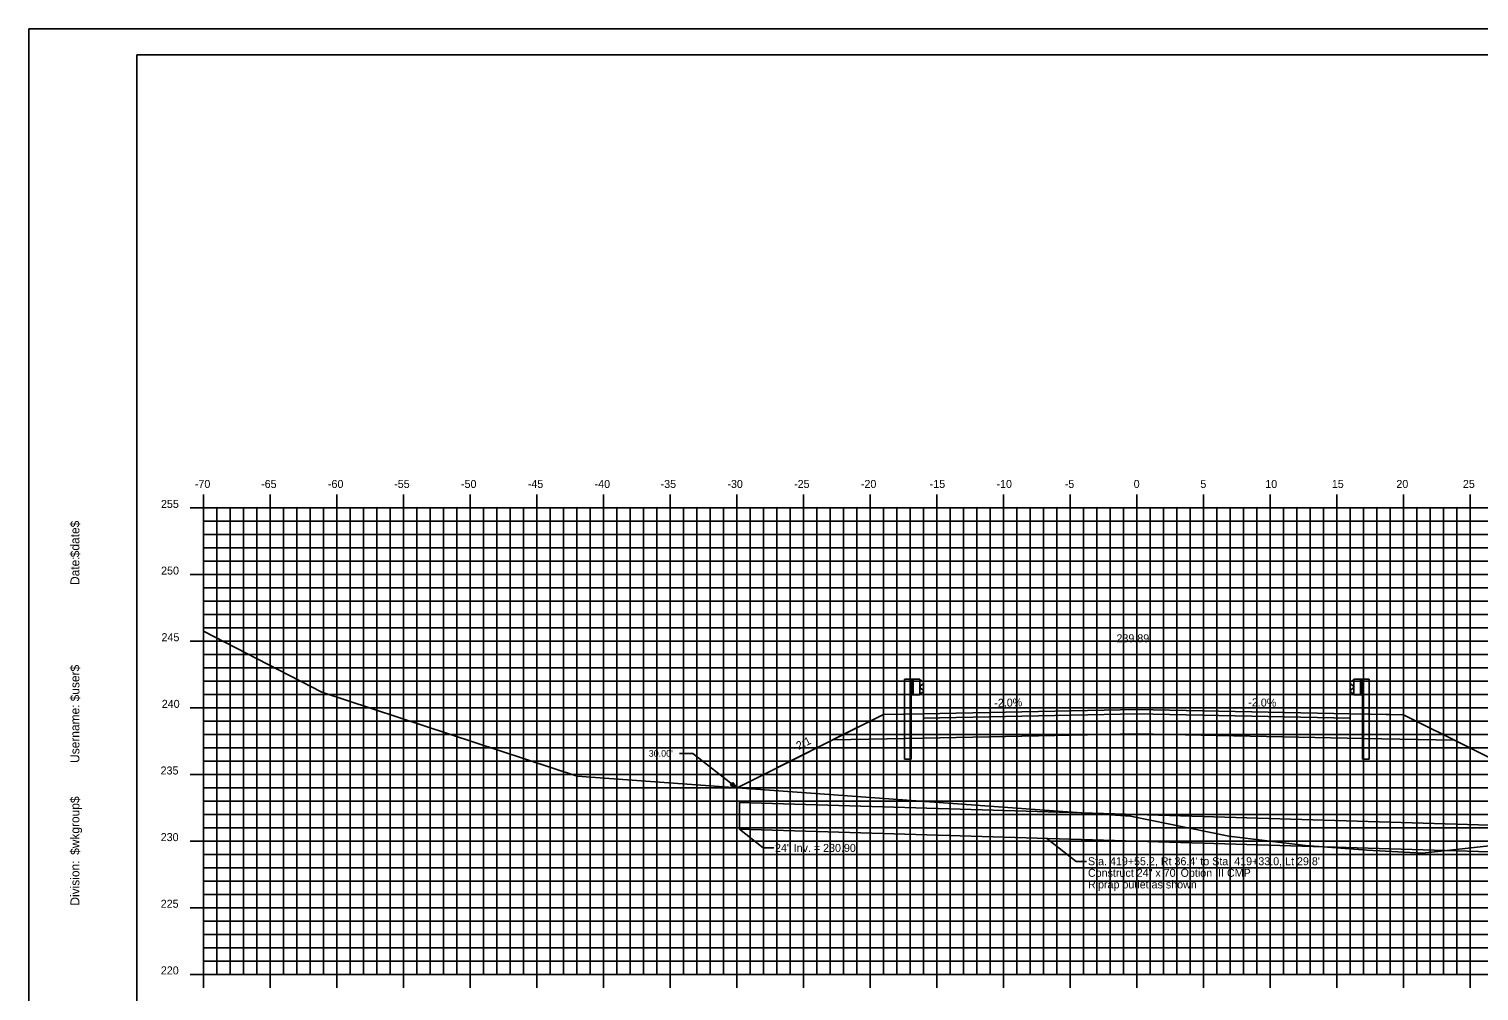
# Model space of a CAD drawing. Extents: x 1160718 to 1173142, y 616002 to 617630.
# Drawn here: x 1169214 to 1169322.8, y 616651.7 to 616723.9 of the extents above; entities that cross this region are included whole.
import ezdxf

# ---------------------------------------------------------------- set-up
doc = ezdxf.new("R2010")
doc.units = 0
for name, color, linetype in [('ANNOTATION', 7, 'Continuous'), ('BORDER', 7, 'Continuous'), ('D_Drainage_Culvert', 7, 'Continuous'), ('D_Guardrail_Beam_Lt', 7, 'Continuous'), ('D_Guardrail_Beam_Rt', 7, 'Continuous'), ('D_Roadway_Centerline', 7, 'Continuous'), ('D_Roadway_Centerline_Text', 7, 'Continuous'), ('D_Roadway_Edge_Shoulder', 7, 'Continuous'), ('D_Roadway_Edge_TW', 7, 'Continuous'), ('D_Roadway_Pavement', 7, 'Continuous'), ('D_Roadway_SlopeLines', 7, 'Continuous'), ('D_Roadway_SubGrade', 7, 'Continuous'), ('H_V ANNOTATION', 7, 'Continuous'), ('MAJOR', 7, 'Continuous'), ('MINOR', 7, 'Continuous'), ('PLOT BOUNDARY', 7, 'Continuous'), ('S_Roadway_Centerline', 7, 'Continuous')]:
    doc.layers.add(name, color=color, linetype=linetype)

msp = doc.modelspace()

# ---------------------------------------------------------------- linework, layer by layer
at = {"layer": 'ANNOTATION'}
for p in [(1169262.82, 616669.51), (1169267.12, 616666.93)]:
    msp.add_line(p, (1169263.82, 616669.51), dxfattribs=at)
msp.add_lwpolyline([(1169274.3, 616670.53), (1169281.12, 616670.66), (1169297.12, 616670.98), (1169314.12, 616670.64), (1169320.94, 616670.51)], dxfattribs=at)
msp.add_lwpolyline([(1169266.81, 616667.34), (1169267.12, 616666.93), (1169266.65, 616667.14)], close=True, dxfattribs=at)
at = {"layer": 'BORDER'}
for p, q in [((1169382.12, 616721.93), (1169222.12, 616721.93)), ((1169222.12, 616721.93), (1169222.12, 616616.93))]:
    msp.add_line(p, q, dxfattribs=at)
at = {"layer": 'D_Drainage_Culvert'}
for p, q in [((1169267.32, 616663.83), (1169267.32, 616665.83)), ((1169333.52, 616663.83), (1169267.32, 616665.83)), ((1169333.52, 616661.83), (1169267.32, 616663.83))]:
    msp.add_line(p, q, dxfattribs=at)
at = {"layer": 'D_Guardrail_Beam_Lt'}
for p, q in [((1169279.7, 616675.08), (1169279.7, 616669.08)), ((1169280.17, 616675.08), (1169279.7, 616675.08)), ((1169280.85, 616675.08), (1169280.17, 616675.08)), ((1169280.17, 616675.08), (1169280.17, 616673.91)), ((1169280.23, 616675.08), (1169280.23, 616673.91)), ((1169280.33, 616675.08), (1169280.33, 616673.91)), ((1169280.85, 616673.91), (1169280.85, 616675.08)), ((1169280.85, 616674.99), (1169280.93, 616674.98)), ((1169280.86, 616674.53), (1169280.86, 616674.46)), ((1169281.09, 616674.73), (1169280.89, 616674.59)), ((1169280.89, 616674.4), (1169281.09, 616674.26)), ((1169280.94, 616674.97), (1169281.09, 616674.87)), ((1169281.09, 616674.12), (1169280.94, 616674.02)), ((1169280.17, 616673.91), (1169280.85, 616673.91)), ((1169280.19, 616669.08), (1169280.19, 616673.91)), ((1169280.93, 616674.01), (1169280.85, 616673.99)), ((1169280.19, 616669.08), (1169279.7, 616669.08))]:
    msp.add_line(p, q, dxfattribs=at)
for centre, major_axis, start_param, end_param in [((1169280.94, 616674.53), (-0.0789, 0), 5.323254, 6.283185), ((1169280.94, 616674.46), (-0.0789, 0), 6.283185, 7.243116), ((1169280.92, 616674.94), (0.0417, 0), 0.959931, 1.376053), ((1169281.04, 616674.8), (0.0877, 0), 5.323254, 7.243116), ((1169281.04, 616674.19), (0.0877, 0), 5.323254, 7.243116), ((1169280.92, 616674.05), (0.0417, 0), 4.907132, 5.323254)]:
    msp.add_ellipse(centre, major_axis=major_axis, ratio=0.995501, start_param=start_param, end_param=end_param, dxfattribs=at)
at = {"layer": 'D_Guardrail_Beam_Rt'}
for p, q in [((1169313.29, 616674.97), (1169313.14, 616674.87)), ((1169313.14, 616674.73), (1169313.34, 616674.59)), ((1169313.34, 616674.4), (1169313.14, 616674.26)), ((1169313.14, 616674.12), (1169313.29, 616674.02)), ((1169313.38, 616675), (1169313.3, 616674.98)), ((1169313.37, 616674.53), (1169313.37, 616674.46)), ((1169313.38, 616675.08), (1169314.06, 616675.08)), ((1169313.38, 616673.91), (1169313.38, 616675.08)), ((1169313.9, 616675.08), (1169313.9, 616673.91)), ((1169314, 616675.08), (1169314, 616673.91)), ((1169314.06, 616675.08), (1169314.53, 616675.08)), ((1169314.06, 616675.08), (1169314.06, 616673.91)), ((1169314.53, 616675.08), (1169314.53, 616669.08)), ((1169313.3, 616674.01), (1169313.38, 616674)), ((1169314.06, 616673.91), (1169313.38, 616673.91)), ((1169314.04, 616669.08), (1169314.04, 616673.91)), ((1169314.04, 616669.08), (1169314.53, 616669.08))]:
    msp.add_line(p, q, dxfattribs=at)
for centre, major_axis, start_param, end_param in [((1169313.19, 616674.8), (-0.0877, 0), 5.323254, 7.243116), ((1169313.19, 616674.19), (-0.0877, 0), 5.323254, 7.243116), ((1169313.31, 616674.94), (-0.0417, 0), 4.907132, 5.323254), ((1169313.29, 616674.53), (0.0789, 0), 0, 0.959931), ((1169313.29, 616674.46), (0.0789, 0), 5.323254, 6.283185), ((1169313.31, 616674.05), (-0.0417, 0), 0.959931, 1.376053)]:
    msp.add_ellipse(centre, major_axis=major_axis, ratio=0.995501, start_param=start_param, end_param=end_param, dxfattribs=at)
at = {"layer": 'D_Roadway_Centerline'}
for p, q in [((1169273.26, 616670), (1169278.12, 616672.43)), ((1169278.12, 616672.43), (1169281.12, 616672.49)), ((1169281.12, 616672.49), (1169297.12, 616672.81)), ((1169297.12, 616672.81), (1169313.12, 616672.49)), ((1169313.12, 616672.49), (1169316.12, 616672.43)), ((1169267.13, 616666.94), (1169273.26, 616670)), ((1169321.99, 616669.98), (1169329.7, 616666.13))]:
    msp.add_line(p, q, dxfattribs=at)
at = {"layer": 'D_Roadway_Centerline_Text'}
for p, q in [((1169269.09, 616662.42), (1169267.32, 616663.83)), ((1169269.88, 616662.42), (1169269.09, 616662.42)), ((1169292.56, 616661.41), (1169290.36, 616663.13)), ((1169293.35, 616661.41), (1169292.56, 616661.41))]:
    msp.add_line(p, q, dxfattribs=at)
at = {"layer": 'D_Roadway_Edge_Shoulder'}
for points in [[(1169281.12, 616672.49), (1169281.12, 616672.16)], [(1169313.12, 616672.49), (1169313.12, 616672.16)]]:
    msp.add_lwpolyline(points, dxfattribs=at)
at = {"layer": 'D_Roadway_Edge_TW'}
msp.add_lwpolyline([(1169281.12, 616672.16), (1169281.12, 616672.49), (1169297.12, 616672.81), (1169313.12, 616672.49), (1169313.12, 616672.16), (1169297.12, 616672.48)], close=True, dxfattribs=at)
at = {"layer": 'D_Roadway_Pavement'}
msp.add_lwpolyline([(1169281.12, 616672.16), (1169281.12, 616672.16), (1169297.12, 616672.48), (1169313.12, 616672.16), (1169313.12, 616672.16), (1169297.12, 616672.48)], close=True, dxfattribs=at)
for points in [[(1169281.12, 616672.16), (1169281.12, 616672.16)], [(1169281.12, 616672.16), (1169281.12, 616672.16)], [(1169313.12, 616672.16), (1169313.12, 616672.16)], [(1169313.12, 616672.16), (1169313.12, 616672.16)]]:
    msp.add_lwpolyline(points, dxfattribs=at)
at = {"layer": 'D_Roadway_SlopeLines'}
msp.add_lwpolyline([(1169278.12, 616672.43), (1169267.13, 616666.94)], dxfattribs=at)
at = {"layer": 'D_Roadway_SubGrade'}
for p, q in [((1169313.12, 616672.49), (1169317.12, 616672.41)), ((1169313.12, 616670.66), (1169313.12, 616672.49)), ((1169317.12, 616672.41), (1169321.99, 616669.98))]:
    msp.add_line(p, q, dxfattribs=at)
for points in [[(1169281.12, 616670.66), (1169281.12, 616672.49), (1169278.12, 616672.43), (1169274.3, 616670.53)], [(1169281.12, 616670.66), (1169281.12, 616672.16), (1169297.12, 616672.48), (1169313.12, 616672.16), (1169313.12, 616670.66)]]:
    msp.add_lwpolyline(points, dxfattribs=at)
at = {"layer": 'MAJOR'}
for p, q in [((1169227.12, 616688.93), (1169227.12, 616687.93)), ((1169232.12, 616688.93), (1169232.12, 616687.93)), ((1169237.12, 616688.93), (1169237.12, 616687.93)), ((1169242.12, 616688.93), (1169242.12, 616687.93)), ((1169247.12, 616688.93), (1169247.12, 616687.93)), ((1169252.12, 616688.93), (1169252.12, 616687.93)), ((1169257.12, 616688.93), (1169257.12, 616687.93)), ((1169262.12, 616688.93), (1169262.12, 616687.93)), ((1169267.12, 616688.93), (1169267.12, 616687.93)), ((1169272.12, 616688.93), (1169272.12, 616687.93)), ((1169277.12, 616688.93), (1169277.12, 616687.93)), ((1169282.12, 616688.93), (1169282.12, 616687.93)), ((1169287.12, 616688.93), (1169287.12, 616687.93)), ((1169292.12, 616688.93), (1169292.12, 616687.93)), ((1169297.12, 616688.93), (1169297.12, 616687.93)), ((1169302.12, 616688.93), (1169302.12, 616687.93)), ((1169307.12, 616688.93), (1169307.12, 616687.93)), ((1169312.12, 616688.93), (1169312.12, 616687.93)), ((1169317.12, 616688.93), (1169317.12, 616687.93)), ((1169322.12, 616688.93), (1169322.12, 616687.93)), ((1169226.12, 616687.93), (1169227.12, 616687.93)), ((1169227.12, 616687.93), (1169367.12, 616687.93)), ((1169227.12, 616652.93), (1169227.12, 616687.93)), ((1169227.12, 616652.93), (1169227.12, 616687.93)), ((1169227.12, 616687.93), (1169367.12, 616687.93)), ((1169232.12, 616652.93), (1169232.12, 616687.93)), ((1169237.12, 616652.93), (1169237.12, 616687.93)), ((1169242.12, 616652.93), (1169242.12, 616687.93)), ((1169247.12, 616652.93), (1169247.12, 616687.93)), ((1169252.12, 616652.93), (1169252.12, 616687.93)), ((1169257.12, 616652.93), (1169257.12, 616687.93)), ((1169262.12, 616652.93), (1169262.12, 616687.93)), ((1169267.12, 616652.93), (1169267.12, 616687.93)), ((1169272.12, 616652.93), (1169272.12, 616687.93)), ((1169277.12, 616652.93), (1169277.12, 616687.93)), ((1169282.12, 616652.93), (1169282.12, 616687.93)), ((1169287.12, 616652.93), (1169287.12, 616687.93)), ((1169292.12, 616652.93), (1169292.12, 616687.93)), ((1169297.12, 616652.93), (1169297.12, 616687.93)), ((1169302.12, 616652.93), (1169302.12, 616687.93)), ((1169307.12, 616652.93), (1169307.12, 616687.93)), ((1169312.12, 616652.93), (1169312.12, 616687.93)), ((1169317.12, 616652.93), (1169317.12, 616687.93)), ((1169322.12, 616652.93), (1169322.12, 616687.93)), ((1169226.12, 616682.93), (1169227.12, 616682.93)), ((1169227.12, 616682.93), (1169367.12, 616682.93)), ((1169226.12, 616677.93), (1169227.12, 616677.93)), ((1169227.12, 616677.93), (1169367.12, 616677.93)), ((1169226.12, 616672.93), (1169227.12, 616672.93)), ((1169227.12, 616672.93), (1169367.12, 616672.93)), ((1169226.12, 616667.93), (1169227.12, 616667.93)), ((1169227.12, 616667.93), (1169367.12, 616667.93)), ((1169226.12, 616662.93), (1169227.12, 616662.93)), ((1169227.12, 616662.93), (1169367.12, 616662.93)), ((1169226.12, 616657.93), (1169227.12, 616657.93)), ((1169227.12, 616657.93), (1169367.12, 616657.93)), ((1169226.12, 616652.93), (1169227.12, 616652.93)), ((1169227.12, 616652.93), (1169367.12, 616652.93)), ((1169227.12, 616652.93), (1169367.12, 616652.93)), ((1169227.12, 616651.93), (1169227.12, 616652.93)), ((1169232.12, 616651.93), (1169232.12, 616652.93)), ((1169237.12, 616651.93), (1169237.12, 616652.93)), ((1169242.12, 616651.93), (1169242.12, 616652.93)), ((1169247.12, 616651.93), (1169247.12, 616652.93)), ((1169252.12, 616651.93), (1169252.12, 616652.93)), ((1169257.12, 616651.93), (1169257.12, 616652.93)), ((1169262.12, 616651.93), (1169262.12, 616652.93)), ((1169267.12, 616651.93), (1169267.12, 616652.93)), ((1169272.12, 616651.93), (1169272.12, 616652.93)), ((1169277.12, 616651.93), (1169277.12, 616652.93)), ((1169282.12, 616651.93), (1169282.12, 616652.93)), ((1169287.12, 616651.93), (1169287.12, 616652.93)), ((1169292.12, 616651.93), (1169292.12, 616652.93)), ((1169297.12, 616651.93), (1169297.12, 616652.93)), ((1169302.12, 616651.93), (1169302.12, 616652.93)), ((1169307.12, 616651.93), (1169307.12, 616652.93)), ((1169312.12, 616651.93), (1169312.12, 616652.93)), ((1169317.12, 616651.93), (1169317.12, 616652.93)), ((1169322.12, 616651.93), (1169322.12, 616652.93))]:
    msp.add_line(p, q, dxfattribs=at)
at = {"layer": 'MINOR'}
for p, q in [((1169228.12, 616652.93), (1169228.12, 616687.93)), ((1169229.12, 616652.93), (1169229.12, 616687.93)), ((1169230.12, 616652.93), (1169230.12, 616687.93)), ((1169231.12, 616652.93), (1169231.12, 616687.93)), ((1169233.12, 616652.93), (1169233.12, 616687.93)), ((1169234.12, 616652.93), (1169234.12, 616687.93)), ((1169235.12, 616652.93), (1169235.12, 616687.93)), ((1169236.12, 616652.93), (1169236.12, 616687.93)), ((1169238.12, 616652.93), (1169238.12, 616687.93)), ((1169239.12, 616652.93), (1169239.12, 616687.93)), ((1169240.12, 616652.93), (1169240.12, 616687.93)), ((1169241.12, 616652.93), (1169241.12, 616687.93)), ((1169243.12, 616652.93), (1169243.12, 616687.93)), ((1169244.12, 616652.93), (1169244.12, 616687.93)), ((1169245.12, 616652.93), (1169245.12, 616687.93)), ((1169246.12, 616652.93), (1169246.12, 616687.93)), ((1169248.12, 616652.93), (1169248.12, 616687.93)), ((1169249.12, 616652.93), (1169249.12, 616687.93)), ((1169250.12, 616652.93), (1169250.12, 616687.93)), ((1169251.12, 616652.93), (1169251.12, 616687.93)), ((1169253.12, 616652.93), (1169253.12, 616687.93)), ((1169254.12, 616652.93), (1169254.12, 616687.93)), ((1169255.12, 616652.93), (1169255.12, 616687.93)), ((1169256.12, 616652.93), (1169256.12, 616687.93)), ((1169258.12, 616652.93), (1169258.12, 616687.93)), ((1169259.12, 616652.93), (1169259.12, 616687.93)), ((1169260.12, 616652.93), (1169260.12, 616687.93)), ((1169261.12, 616652.93), (1169261.12, 616687.93)), ((1169263.12, 616652.93), (1169263.12, 616687.93)), ((1169264.12, 616652.93), (1169264.12, 616687.93)), ((1169265.12, 616652.93), (1169265.12, 616687.93)), ((1169266.12, 616652.93), (1169266.12, 616687.93)), ((1169268.12, 616652.93), (1169268.12, 616687.93)), ((1169269.12, 616652.93), (1169269.12, 616687.93)), ((1169270.12, 616652.93), (1169270.12, 616687.93)), ((1169271.12, 616652.93), (1169271.12, 616687.93)), ((1169273.12, 616652.93), (1169273.12, 616687.93)), ((1169274.12, 616652.93), (1169274.12, 616687.93)), ((1169275.12, 616652.93), (1169275.12, 616687.93)), ((1169276.12, 616652.93), (1169276.12, 616687.93)), ((1169278.12, 616652.93), (1169278.12, 616687.93)), ((1169279.12, 616652.93), (1169279.12, 616687.93)), ((1169280.12, 616652.93), (1169280.12, 616687.93)), ((1169281.12, 616652.93), (1169281.12, 616687.93)), ((1169283.12, 616652.93), (1169283.12, 616687.93)), ((1169284.12, 616652.93), (1169284.12, 616687.93)), ((1169285.12, 616652.93), (1169285.12, 616687.93)), ((1169286.12, 616652.93), (1169286.12, 616687.93)), ((1169288.12, 616652.93), (1169288.12, 616687.93)), ((1169289.12, 616652.93), (1169289.12, 616687.93)), ((1169290.12, 616652.93), (1169290.12, 616687.93)), ((1169291.12, 616652.93), (1169291.12, 616687.93)), ((1169293.12, 616652.93), (1169293.12, 616687.93)), ((1169294.12, 616652.93), (1169294.12, 616687.93)), ((1169295.12, 616652.93), (1169295.12, 616687.93)), ((1169296.12, 616652.93), (1169296.12, 616687.93)), ((1169298.12, 616652.93), (1169298.12, 616687.93)), ((1169299.12, 616652.93), (1169299.12, 616687.93)), ((1169300.12, 616652.93), (1169300.12, 616687.93)), ((1169301.12, 616652.93), (1169301.12, 616687.93)), ((1169303.12, 616652.93), (1169303.12, 616687.93)), ((1169304.12, 616652.93), (1169304.12, 616687.93)), ((1169305.12, 616652.93), (1169305.12, 616687.93)), ((1169306.12, 616652.93), (1169306.12, 616687.93)), ((1169308.12, 616652.93), (1169308.12, 616687.93)), ((1169309.12, 616652.93), (1169309.12, 616687.93)), ((1169310.12, 616652.93), (1169310.12, 616687.93)), ((1169311.12, 616652.93), (1169311.12, 616687.93)), ((1169313.12, 616652.93), (1169313.12, 616687.93)), ((1169314.12, 616652.93), (1169314.12, 616687.93)), ((1169315.12, 616652.93), (1169315.12, 616687.93)), ((1169316.12, 616652.93), (1169316.12, 616687.93)), ((1169318.12, 616652.93), (1169318.12, 616687.93)), ((1169319.12, 616652.93), (1169319.12, 616687.93)), ((1169320.12, 616652.93), (1169320.12, 616687.93)), ((1169321.12, 616652.93), (1169321.12, 616687.93)), ((1169227.12, 616686.93), (1169367.12, 616686.93)), ((1169227.12, 616686.93), (1169228.13, 616686.93)), ((1169227.12, 616685.93), (1169367.12, 616685.93)), ((1169227.12, 616685.93), (1169228.13, 616685.93)), ((1169227.12, 616684.93), (1169367.12, 616684.93)), ((1169227.12, 616684.93), (1169228.13, 616684.93)), ((1169227.12, 616683.93), (1169367.12, 616683.93)), ((1169227.12, 616683.93), (1169228.13, 616683.93)), ((1169227.12, 616681.93), (1169367.12, 616681.93)), ((1169227.12, 616681.93), (1169228.13, 616681.93)), ((1169227.12, 616680.93), (1169367.12, 616680.93)), ((1169227.12, 616680.93), (1169228.13, 616680.93)), ((1169227.12, 616679.93), (1169367.12, 616679.93)), ((1169227.12, 616679.93), (1169228.13, 616679.93)), ((1169227.12, 616678.93), (1169367.12, 616678.93)), ((1169227.12, 616678.93), (1169228.13, 616678.93)), ((1169227.12, 616676.93), (1169367.12, 616676.93)), ((1169227.12, 616676.93), (1169228.13, 616676.93)), ((1169227.12, 616675.93), (1169367.12, 616675.93)), ((1169227.12, 616675.93), (1169228.13, 616675.93)), ((1169227.12, 616674.93), (1169367.12, 616674.93)), ((1169227.12, 616674.93), (1169228.13, 616674.93)), ((1169227.12, 616673.93), (1169367.12, 616673.93)), ((1169227.12, 616673.93), (1169228.13, 616673.93)), ((1169227.12, 616671.93), (1169367.12, 616671.93)), ((1169227.12, 616671.93), (1169228.13, 616671.93)), ((1169227.12, 616670.93), (1169367.12, 616670.93)), ((1169227.12, 616670.93), (1169228.13, 616670.93)), ((1169227.12, 616669.93), (1169367.12, 616669.93)), ((1169227.12, 616669.93), (1169228.13, 616669.93)), ((1169227.12, 616668.93), (1169367.12, 616668.93)), ((1169227.12, 616668.93), (1169228.13, 616668.93)), ((1169227.12, 616666.93), (1169367.12, 616666.93)), ((1169227.12, 616666.93), (1169228.13, 616666.93)), ((1169227.12, 616665.93), (1169367.12, 616665.93)), ((1169227.12, 616665.93), (1169228.13, 616665.93)), ((1169227.12, 616664.93), (1169367.12, 616664.93)), ((1169227.12, 616664.93), (1169228.13, 616664.93)), ((1169227.12, 616663.93), (1169367.12, 616663.93)), ((1169227.12, 616663.93), (1169228.13, 616663.93)), ((1169227.12, 616661.93), (1169367.12, 616661.93)), ((1169227.12, 616661.93), (1169228.13, 616661.93)), ((1169227.12, 616660.93), (1169367.12, 616660.93)), ((1169227.12, 616660.93), (1169228.13, 616660.93)), ((1169227.12, 616659.93), (1169367.12, 616659.93)), ((1169227.12, 616659.93), (1169228.13, 616659.93)), ((1169227.12, 616658.93), (1169367.12, 616658.93)), ((1169227.12, 616658.93), (1169228.13, 616658.93)), ((1169227.12, 616656.93), (1169367.12, 616656.93)), ((1169227.12, 616656.93), (1169228.13, 616656.93)), ((1169227.12, 616655.93), (1169367.12, 616655.93)), ((1169227.12, 616655.93), (1169228.13, 616655.93)), ((1169227.12, 616654.93), (1169367.12, 616654.93)), ((1169227.12, 616654.93), (1169228.13, 616654.93)), ((1169227.12, 616653.93), (1169367.12, 616653.93)), ((1169227.12, 616653.93), (1169228.13, 616653.93))]:
    msp.add_line(p, q, dxfattribs=at)
at = {"layer": 'PLOT BOUNDARY'}
msp.add_lwpolyline([(1169214.03, 616613.87), (1169384.03, 616613.87), (1169384.03, 616723.87), (1169214.03, 616723.87)], close=True, dxfattribs=at)
at = {"layer": 'S_Roadway_Centerline'}
msp.add_lwpolyline([(1169227.12, 616678.69), (1169236, 616674.1), (1169255.15, 616667.81), (1169291.22, 616665.18), (1169294.76, 616664.93), (1169296.65, 616664.81), (1169304.02, 616663.29), (1169309.76, 616662.61), (1169314.38, 616662.25), (1169318.55, 616662.02), (1169324.25, 616662.64)], dxfattribs=at)

# ---------------------------------------------------------------- texts
at = {"layer": 'ANNOTATION'}
for s, rotation, p in [('-2.0%', 1.1458, (1169286.43, 616673)), ('-2.0%', 358.8542, (1169305.47, 616673.05)), ('-2:1', 26.5651, (1169271.51, 616669.65))]:
    msp.add_text(s, height=0.6, rotation=rotation, dxfattribs=at).set_placement(p)
msp.add_text("30.00'", height=0.5, dxfattribs=at).set_placement((1169260.51, 616669.26))
at = {"layer": 'BORDER'}
for s, p in [('$date$', (1169217.81, 616684.23)), ('Date:', (1169217.81, 616682.15)), ('$user$', (1169217.81, 616673.42)), ('Username:', (1169217.81, 616668.8)), ('$wkgroup$', (1169217.81, 616661.9)), ('Division:', (1169217.81, 616658.09))]:
    msp.add_text(s, height=0.67, rotation=90, dxfattribs=at).set_placement(p)
at = {"layer": 'D_Roadway_Centerline'}
for s in ['C', 'L']:
    msp.add_text(s, height=0.0146, dxfattribs=at).set_placement((1169297.12, 616672.81))
at = {"layer": 'D_Roadway_Centerline_Text'}
for s, p in [('239.89', (1169295.59, 616677.85)), ('24" Inv. = 230.90', (1169269.98, 616662.12)), ("Sta. 419+55.2, Rt 36.4' to Sta. 419+33.0, Lt 29.8'", (1169293.45, 616661.12)), ('Construct 24" x 70\' Option III CMP', (1169293.45, 616660.25)), ('Riprap outlet as shown', (1169293.45, 616659.38))]:
    msp.add_text(s, height=0.6, dxfattribs=at).set_placement(p)
at = {"layer": 'H_V ANNOTATION'}
for s, p in [('-70', (1169226.47, 616689.43)), ('-65', (1169231.44, 616689.43)), ('-60', (1169236.45, 616689.43)), ('-55', (1169241.42, 616689.43)), ('-50', (1169246.43, 616689.43)), ('-45', (1169251.44, 616689.43)), ('-40', (1169256.45, 616689.43)), ('-35', (1169261.4, 616689.43)), ('-30', (1169266.41, 616689.43)), ('-25', (1169271.41, 616689.43)), ('-20', (1169276.42, 616689.43)), ('-15', (1169281.58, 616689.43)), ('-10', (1169286.59, 616689.43)), ('-5', (1169291.71, 616689.43)), ('0', (1169296.88, 616689.43)), ('5', (1169301.88, 616689.43)), ('10', (1169306.75, 616689.43)), ('15', (1169311.74, 616689.43)), ('20', (1169316.58, 616689.43)), ('25', (1169321.57, 616689.43)), ('255', (1169223.93, 616687.93)), ('250', (1169223.94, 616682.93)), ('245', (1169223.97, 616677.93)), ('240', (1169223.99, 616672.93)), ('235', (1169223.9, 616667.93)), ('230', (1169223.91, 616662.93)), ('225', (1169223.91, 616657.93)), ('220', (1169223.92, 616652.93))]:
    msp.add_text(s, height=0.6, dxfattribs=at).set_placement(p)

doc.saveas('drawing.dxf')
